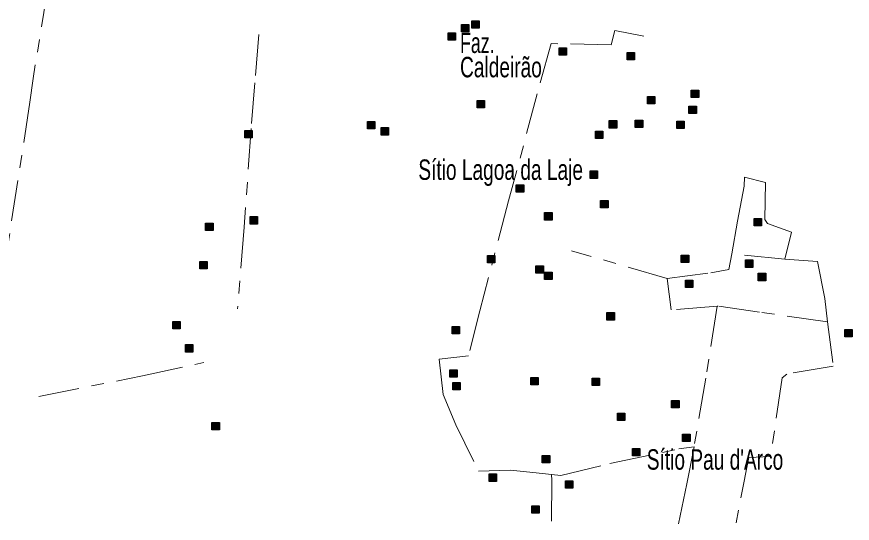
# Model space of a CAD drawing. Extents: x 445.4 to 500, y 8728.7 to 8784.
# Drawn here: x 475.26 to 481.81, y 8774.71 to 8778.68 of the extents above; entities that cross this region are included whole.
import ezdxf

# ---------------------------------------------------------------- set-up
doc = ezdxf.new("R2010")
doc.units = 0
doc.header["$LTSCALE"] = 0.064
doc.linetypes.add('DOT_DASHED', pattern=[7.7, 5, -1.2, 0.3, -1.2])
doc.layers.add('2', color=7, linetype='Continuous', lineweight=25)
doc.layers.add('22', color=7, linetype='DOT_DASHED', lineweight=13)
doc.layers.add('61', color=7, linetype='Continuous')

msp = doc.modelspace()

# ---------------------------------------------------------------- hatches: boundary and pattern name
at = {"layer": '2'}
for points in [[(478.825, 8778.644), (478.883, 8778.644), (478.883, 8778.586), (478.825, 8778.586)], [(478.7435, 8778.6169), (478.8015, 8778.6169), (478.8015, 8778.5589), (478.7435, 8778.5589)], [(478.6394, 8778.5507), (478.6974, 8778.5507), (478.6974, 8778.4927), (478.6394, 8778.4927)], [(479.5081, 8778.4328), (479.5661, 8778.4328), (479.5661, 8778.3748), (479.5081, 8778.3748)], [(480.0422, 8778.3968), (480.1002, 8778.3968), (480.1002, 8778.3388), (480.0422, 8778.3388)], [(480.2006, 8778.0527), (480.2586, 8778.0527), (480.2586, 8777.9947), (480.2006, 8777.9947)], [(480.5445, 8778.1025), (480.6025, 8778.1025), (480.6025, 8778.0445), (480.5445, 8778.0445)], [(478.8657, 8778.021), (478.9237, 8778.021), (478.9237, 8777.963), (478.8657, 8777.963)], [(480.5264, 8777.9757), (480.5844, 8777.9757), (480.5844, 8777.9177), (480.5264, 8777.9177)], [(478.0068, 8777.8573), (478.0648, 8777.8573), (478.0648, 8777.7993), (478.0068, 8777.7993)], [(479.9019, 8777.8626), (479.9599, 8777.8626), (479.9599, 8777.8046), (479.9019, 8777.8046)], [(480.1055, 8777.8671), (480.1635, 8777.8671), (480.1635, 8777.8091), (480.1055, 8777.8091)], [(480.4313, 8777.858), (480.4893, 8777.858), (480.4893, 8777.8), (480.4313, 8777.8)], [(477.0466, 8777.7856), (477.1046, 8777.7856), (477.1046, 8777.7276), (477.0466, 8777.7276)], [(478.1145, 8777.8082), (478.1725, 8777.8082), (478.1725, 8777.7502), (478.1145, 8777.7502)], [(479.7933, 8777.7811), (479.8513, 8777.7811), (479.8513, 8777.7231), (479.7933, 8777.7231)], [(479.7526, 8777.4687), (479.8106, 8777.4687), (479.8106, 8777.4107), (479.7526, 8777.4107)], [(479.1734, 8777.36), (479.2314, 8777.36), (479.2314, 8777.302), (479.1734, 8777.302)], [(479.834, 8777.2378), (479.892, 8777.2378), (479.892, 8777.1798), (479.834, 8777.1798)], [(479.3951, 8777.1427), (479.4531, 8777.1427), (479.4531, 8777.0847), (479.3951, 8777.0847)], [(476.7389, 8777.0612), (476.7969, 8777.0612), (476.7969, 8777.0032), (476.7389, 8777.0032)], [(477.0874, 8777.111), (477.1454, 8777.111), (477.1454, 8777.053), (477.0874, 8777.053)], [(481.0377, 8777.0977), (481.0957, 8777.0977), (481.0957, 8777.0397), (481.0377, 8777.0397)], [(478.9471, 8776.8077), (479.0051, 8776.8077), (479.0051, 8776.7497), (478.9471, 8776.7497)], [(480.4663, 8776.8103), (480.5243, 8776.8103), (480.5243, 8776.7523), (480.4663, 8776.7523)], [(476.6936, 8776.7606), (476.7516, 8776.7606), (476.7516, 8776.7026), (476.6936, 8776.7026)], [(480.9698, 8776.7717), (481.0278, 8776.7717), (481.0278, 8776.7137), (480.9698, 8776.7137)], [(479.3272, 8776.7262), (479.3852, 8776.7262), (479.3852, 8776.6682), (479.3272, 8776.6682)], [(479.3951, 8776.6764), (479.4531, 8776.6764), (479.4531, 8776.6184), (479.3951, 8776.6184)], [(481.0694, 8776.6676), (481.1274, 8776.6676), (481.1274, 8776.6096), (481.0694, 8776.6096)], [(480.4992, 8776.613), (480.5572, 8776.613), (480.5572, 8776.555), (480.4992, 8776.555)], [(479.8838, 8776.3595), (479.9418, 8776.3595), (479.9418, 8776.3015), (479.8838, 8776.3015)], [(476.481, 8776.2898), (476.539, 8776.2898), (476.539, 8776.2318), (476.481, 8776.2318)], [(478.6711, 8776.2508), (478.7291, 8776.2508), (478.7291, 8776.1928), (478.6711, 8776.1928)], [(481.7481, 8776.2285), (481.8061, 8776.2285), (481.8061, 8776.1705), (481.7481, 8776.1705)], [(476.5805, 8776.1087), (476.6385, 8776.1087), (476.6385, 8776.0507), (476.5805, 8776.0507)], [(478.653, 8775.9112), (478.711, 8775.9112), (478.711, 8775.8532), (478.653, 8775.8532)], [(479.2865, 8775.8524), (479.3445, 8775.8524), (479.3445, 8775.7944), (479.2865, 8775.7944)], [(479.7672, 8775.8457), (479.8252, 8775.8457), (479.8252, 8775.7877), (479.7672, 8775.7877)], [(478.6756, 8775.8116), (478.7336, 8775.8116), (478.7336, 8775.7536), (478.6756, 8775.7536)], [(480.3906, 8775.6713), (480.4486, 8775.6713), (480.4486, 8775.6133), (480.3906, 8775.6133)], [(479.9653, 8775.5717), (480.0233, 8775.5717), (480.0233, 8775.5137), (479.9653, 8775.5137)], [(476.7887, 8775.4992), (476.8467, 8775.4992), (476.8467, 8775.4412), (476.7887, 8775.4412)], [(480.4766, 8775.4087), (480.5346, 8775.4087), (480.5346, 8775.3507), (480.4766, 8775.3507)], [(480.0829, 8775.2955), (480.1409, 8775.2955), (480.1409, 8775.2375), (480.0829, 8775.2375)], [(479.377, 8775.2412), (479.435, 8775.2412), (479.435, 8775.1832), (479.377, 8775.1832)], [(478.9607, 8775.0963), (479.0187, 8775.0963), (479.0187, 8775.0383), (478.9607, 8775.0383)], [(479.558, 8775.042), (479.616, 8775.042), (479.616, 8774.984), (479.558, 8774.984)], [(479.2956, 8774.8473), (479.3536, 8774.8473), (479.3536, 8774.7893), (479.2956, 8774.7893)]]:
    msp.add_hatch(color=256, dxfattribs=at).paths.add_polyline_path(points)

# ---------------------------------------------------------------- linework, layer by layer
for points in [[(478.825, 8778.644), (478.883, 8778.644), (478.883, 8778.586), (478.825, 8778.586)], [(478.7435, 8778.6169), (478.8015, 8778.6169), (478.8015, 8778.5589), (478.7435, 8778.5589)], [(478.6394, 8778.5507), (478.6974, 8778.5507), (478.6974, 8778.4927), (478.6394, 8778.4927)], [(479.5081, 8778.4328), (479.5661, 8778.4328), (479.5661, 8778.3748), (479.5081, 8778.3748)], [(480.0422, 8778.3968), (480.1002, 8778.3968), (480.1002, 8778.3388), (480.0422, 8778.3388)], [(480.2006, 8778.0527), (480.2586, 8778.0527), (480.2586, 8777.9947), (480.2006, 8777.9947)], [(480.5445, 8778.1025), (480.6025, 8778.1025), (480.6025, 8778.0445), (480.5445, 8778.0445)], [(478.8657, 8778.021), (478.9237, 8778.021), (478.9237, 8777.963), (478.8657, 8777.963)], [(480.5264, 8777.9757), (480.5844, 8777.9757), (480.5844, 8777.9177), (480.5264, 8777.9177)], [(478.0068, 8777.8573), (478.0648, 8777.8573), (478.0648, 8777.7993), (478.0068, 8777.7993)], [(479.9019, 8777.8626), (479.9599, 8777.8626), (479.9599, 8777.8046), (479.9019, 8777.8046)], [(480.1055, 8777.8671), (480.1635, 8777.8671), (480.1635, 8777.8091), (480.1055, 8777.8091)], [(480.4313, 8777.858), (480.4893, 8777.858), (480.4893, 8777.8), (480.4313, 8777.8)], [(477.0466, 8777.7856), (477.1046, 8777.7856), (477.1046, 8777.7276), (477.0466, 8777.7276)], [(478.1145, 8777.8082), (478.1725, 8777.8082), (478.1725, 8777.7502), (478.1145, 8777.7502)], [(479.7933, 8777.7811), (479.8513, 8777.7811), (479.8513, 8777.7231), (479.7933, 8777.7231)], [(479.7526, 8777.4687), (479.8106, 8777.4687), (479.8106, 8777.4107), (479.7526, 8777.4107)], [(479.1734, 8777.36), (479.2314, 8777.36), (479.2314, 8777.302), (479.1734, 8777.302)], [(479.834, 8777.2378), (479.892, 8777.2378), (479.892, 8777.1798), (479.834, 8777.1798)], [(479.3951, 8777.1427), (479.4531, 8777.1427), (479.4531, 8777.0847), (479.3951, 8777.0847)], [(476.7389, 8777.0612), (476.7969, 8777.0612), (476.7969, 8777.0032), (476.7389, 8777.0032)], [(477.0874, 8777.111), (477.1454, 8777.111), (477.1454, 8777.053), (477.0874, 8777.053)], [(481.0377, 8777.0977), (481.0957, 8777.0977), (481.0957, 8777.0397), (481.0377, 8777.0397)], [(478.9471, 8776.8077), (479.0051, 8776.8077), (479.0051, 8776.7497), (478.9471, 8776.7497)], [(480.4663, 8776.8103), (480.5243, 8776.8103), (480.5243, 8776.7523), (480.4663, 8776.7523)], [(476.6936, 8776.7606), (476.7516, 8776.7606), (476.7516, 8776.7026), (476.6936, 8776.7026)], [(480.9698, 8776.7717), (481.0278, 8776.7717), (481.0278, 8776.7137), (480.9698, 8776.7137)], [(479.3272, 8776.7262), (479.3852, 8776.7262), (479.3852, 8776.6682), (479.3272, 8776.6682)], [(479.3951, 8776.6764), (479.4531, 8776.6764), (479.4531, 8776.6184), (479.3951, 8776.6184)], [(481.0694, 8776.6676), (481.1274, 8776.6676), (481.1274, 8776.6096), (481.0694, 8776.6096)], [(480.4992, 8776.613), (480.5572, 8776.613), (480.5572, 8776.555), (480.4992, 8776.555)], [(479.8838, 8776.3595), (479.9418, 8776.3595), (479.9418, 8776.3015), (479.8838, 8776.3015)], [(476.481, 8776.2898), (476.539, 8776.2898), (476.539, 8776.2318), (476.481, 8776.2318)], [(478.6711, 8776.2508), (478.7291, 8776.2508), (478.7291, 8776.1928), (478.6711, 8776.1928)], [(481.7481, 8776.2285), (481.8061, 8776.2285), (481.8061, 8776.1705), (481.7481, 8776.1705)], [(476.5805, 8776.1087), (476.6385, 8776.1087), (476.6385, 8776.0507), (476.5805, 8776.0507)], [(478.653, 8775.9112), (478.711, 8775.9112), (478.711, 8775.8532), (478.653, 8775.8532)], [(479.2865, 8775.8524), (479.3445, 8775.8524), (479.3445, 8775.7944), (479.2865, 8775.7944)], [(479.7672, 8775.8457), (479.8252, 8775.8457), (479.8252, 8775.7877), (479.7672, 8775.7877)], [(478.6756, 8775.8116), (478.7336, 8775.8116), (478.7336, 8775.7536), (478.6756, 8775.7536)], [(480.3906, 8775.6713), (480.4486, 8775.6713), (480.4486, 8775.6133), (480.3906, 8775.6133)], [(479.9653, 8775.5717), (480.0233, 8775.5717), (480.0233, 8775.5137), (479.9653, 8775.5137)], [(476.7887, 8775.4992), (476.8467, 8775.4992), (476.8467, 8775.4412), (476.7887, 8775.4412)], [(480.4766, 8775.4087), (480.5346, 8775.4087), (480.5346, 8775.3507), (480.4766, 8775.3507)], [(480.0829, 8775.2955), (480.1409, 8775.2955), (480.1409, 8775.2375), (480.0829, 8775.2375)], [(479.377, 8775.2412), (479.435, 8775.2412), (479.435, 8775.1832), (479.377, 8775.1832)], [(478.9607, 8775.0963), (479.0187, 8775.0963), (479.0187, 8775.0383), (478.9607, 8775.0383)], [(479.558, 8775.042), (479.616, 8775.042), (479.616, 8774.984), (479.558, 8774.984)], [(479.2956, 8774.8473), (479.3536, 8774.8473), (479.3536, 8774.7893), (479.2956, 8774.7893)]]:
    msp.add_lwpolyline(points, close=True, dxfattribs=at)
at = {"layer": '22'}
msp.add_line((481.2786, 8776.7772), (480.8611, 8776.82), dxfattribs=at)
for points in [[(475.5987, 8779.571), (475.5049, 8778.9128), (475.3863, 8778.1926), (475.3626, 8778.0078), (475.196, 8776.9328), (475.1296, 8776.4874), (475.1055, 8776.3224)], [(480.1731, 8778.5251), (479.9448, 8778.5685), (479.9179, 8778.4557), (479.4473, 8778.4664), (479.337, 8778.0716), (479.113, 8777.2344), (478.8866, 8776.3725), (478.7977, 8776.021), (478.5684, 8775.9951), (478.6002, 8775.7182), (478.7002, 8775.4821), (478.8775, 8775.119), (479.1287, 8775.1258), (479.3774, 8775.1003), (479.4489, 8775.0928)], [(477.1558, 8778.5362), (477.1255, 8778.1601), (477.096, 8777.8007), (477.0401, 8777.0279), (476.9898, 8776.3886)], [(481.1252, 8777.3782), (480.962, 8777.4191), (480.9582, 8777.3506), (480.9071, 8777.0757), (480.8611, 8776.82)], [(481.2786, 8776.7772), (481.3298, 8776.9904), (481.1419, 8777.0586), (481.1206, 8777.0884), (481.1252, 8777.3782)], [(480.7474, 8776.4099), (480.3862, 8776.3806), (480.3563, 8776.6279), (479.6069, 8776.8443)], [(480.3563, 8776.6279), (480.6979, 8776.6705), (480.8388, 8776.6961), (480.8611, 8776.82)], [(481.2786, 8776.7772), (481.5348, 8776.7601), (481.5903, 8776.4701), (481.6116, 8776.2868)], [(480.7474, 8776.4099), (480.6591, 8775.8459), (480.5658, 8775.3073)], [(481.6116, 8776.2868), (481.0779, 8776.3635), (480.7534, 8776.4104), (480.7474, 8776.4099)], [(481.6116, 8776.2868), (481.6575, 8775.9404), (481.2924, 8775.8785), (481.2571, 8775.8483), (481.1663, 8775.2339), (480.9949, 8775.2238), (480.8234, 8774.3426), (480.3847, 8774.4181)], [(475.4323, 8775.7036), (476.2446, 8775.8643), (476.7256, 8775.9699)], [(479.4489, 8775.0928), (479.5233, 8775.085), (479.9071, 8775.177), (480.4463, 8775.292), (480.5658, 8775.3073)], [(480.5658, 8775.3073), (480.5084, 8775.0198), (480.3847, 8774.4181), (480.3157, 8774.1316)], [(479.4489, 8775.0928), (479.453, 8775.0464), (479.4453, 8774.2049)]]:
    msp.add_lwpolyline(points, dxfattribs=at)

# ---------------------------------------------------------------- texts
at = {"layer": '61'}
for s, width, p in [('Faz.', 0.65, (478.7325, 8778.3922)), ('Caldeirão', 0.7, (478.7325, 8778.2022)), ('Sítio Lagoa da Laje', 0.7, (478.4055, 8777.3989)), ("Sítio Pau d'Arco", 0.7, (480.1957, 8775.1295))]:
    msp.add_text(s, height=0.16, dxfattribs=dict(at, width=width)).set_placement(p)

doc.saveas('drawing.dxf')
